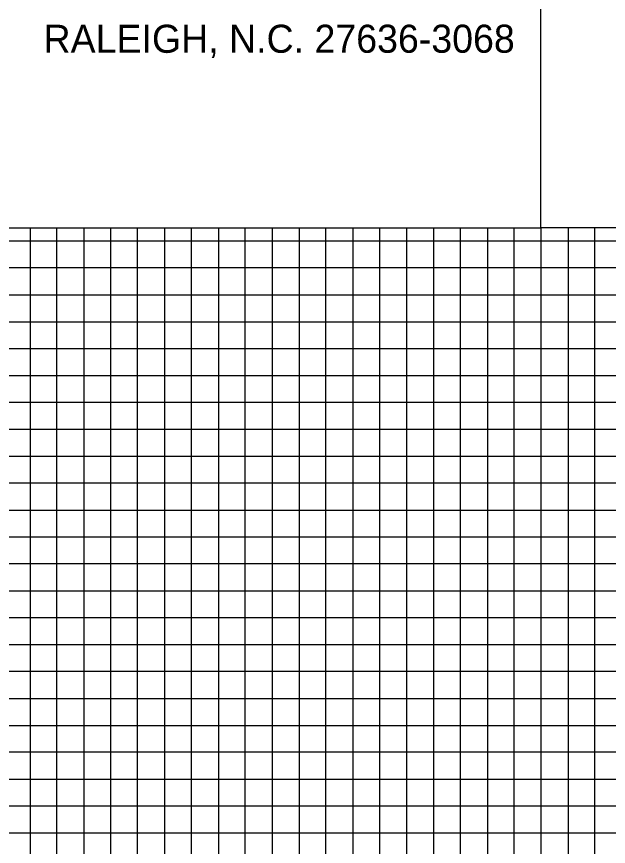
# Model space of a CAD drawing. Extents: x 2431000 to 2534000, y 645879 to 714000.
# Drawn here: x 2468176.3 to 2468286.3, y 669664.6 to 669818.8 of the extents above; entities that cross this region are included whole.
import ezdxf

# ---------------------------------------------------------------- set-up
doc = ezdxf.new("R2010")
doc.units = 0
for name, color, linetype in [('KHA_LOGO', 7, 'Continuous'), ('Sheet Profile CELL', 7, 'Continuous'), ('Sheet Profile Grid Major CELL', 7, 'Continuous'), ('Sheet Profile Grid Middle CELL', 7, 'Continuous'), ('Sheet Profile Grid Minor CELL', 7, 'Continuous')]:
    doc.layers.add(name, color=color, linetype=linetype)

msp = doc.modelspace()

# ---------------------------------------------------------------- linework, layer by layer
at = {"layer": 'KHA_LOGO'}
msp.add_lwpolyline([(2468173.7, 669779.51), (2468273.7, 669779.51), (2468273.7, 669917.06), (2468173.7, 669917.06)], close=True, dxfattribs=at)
at = {"layer": 'Sheet Profile CELL'}
msp.add_lwpolyline([(2468273.7, 669892.01), (2468373.75, 669892.01), (2468373.75, 669779.51), (2468273.7, 669779.51)], close=True, dxfattribs=at)
at = {"layer": 'Sheet Profile Grid Major CELL'}
for points in [[(2468173.75, 669817.06), (2466973.75, 669817.06), (2466973.75, 669767.06), (2468473.75, 669767.06)], [(2468273.75, 669817.06), (2468273.7, 669817.06)], [(2468223.75, 669779.51), (2468223.75, 669417.06), (2468273.75, 669417.06), (2468273.75, 669779.51)], [(2468473.75, 669717.06), (2466973.75, 669717.06), (2466973.75, 669667.06), (2468473.75, 669667.06)]]:
    msp.add_lwpolyline(points, dxfattribs=at)
at = {"layer": 'Sheet Profile Grid Middle CELL'}
for points in [[(2467698.75, 669917.06), (2467748.75, 669917.06), (2467748.75, 669417.06), (2467798.75, 669417.06), (2467798.75, 669917.06), (2467848.75, 669917.06), (2467848.75, 669417.06), (2467898.75, 669417.06), (2467898.75, 669917.06), (2467948.75, 669917.06), (2467948.75, 669417.06), (2467998.75, 669417.06), (2467998.75, 669917.06), (2468048.75, 669917.06), (2468048.75, 669417.06), (2468098.75, 669417.06), (2468098.75, 669917.06), (2468148.75, 669917.06), (2468148.75, 669417.06), (2468198.75, 669417.06), (2468198.75, 669779.51)], [(2468248.75, 669779.51), (2468248.75, 669417.06), (2468298.75, 669417.06), (2468298.75, 669779.51)], [(2468473.75, 669742.06), (2466973.75, 669742.06), (2466973.75, 669692.06), (2468298.75, 669692.06)]]:
    msp.add_lwpolyline(points, dxfattribs=at)
at = {"layer": 'Sheet Profile Grid Minor CELL'}
for p, q in [((2468423.75, 669777.06), (2467023.75, 669777.06)), ((2468423.75, 669772.06), (2467023.75, 669772.06)), ((2467023.75, 669762.06), (2468423.75, 669762.06)), ((2468423.75, 669757.06), (2467023.75, 669757.06)), ((2467023.75, 669752.06), (2468423.75, 669752.06)), ((2468423.75, 669732.06), (2467023.75, 669732.06)), ((2467023.75, 669727.06), (2468423.75, 669727.06)), ((2468423.75, 669707.06), (2467023.75, 669707.06)), ((2467023.75, 669702.06), (2468423.75, 669702.06)), ((2468423.75, 669682.06), (2467023.75, 669682.06)), ((2467023.75, 669677.06), (2468423.75, 669677.06)), ((2468423.75, 669672.06), (2467023.75, 669672.06))]:
    msp.add_line(p, q, dxfattribs=at)
for points in [[(2468273.7, 669812.06), (2468273.75, 669812.06)], [(2468273.75, 669806.96), (2468273.7, 669806.96)], [(2468273.7, 669802.06), (2468273.75, 669802.06)], [(2468273.75, 669797.06), (2468273.7, 669797.06)], [(2468273.7, 669787.06), (2468273.75, 669787.06)], [(2468178.75, 669779.51), (2468178.75, 669417.06), (2468183.75, 669417.06), (2468183.75, 669779.51)], [(2468188.75, 669779.51), (2468188.75, 669417.06), (2468193.75, 669417.06), (2468193.75, 669779.51)], [(2468203.75, 669779.51), (2468203.75, 669417.06), (2468208.75, 669417.06), (2468208.75, 669779.51)], [(2468213.75, 669779.51), (2468213.75, 669417.06), (2468218.75, 669417.06), (2468218.75, 669779.51)], [(2468228.75, 669779.51), (2468228.75, 669417.06), (2468233.75, 669417.06), (2468233.75, 669779.51)], [(2468238.75, 669779.51), (2468238.75, 669417.06), (2468243.75, 669417.06), (2468243.75, 669779.51)], [(2468253.75, 669779.51), (2468253.75, 669417.06), (2468258.75, 669417.06), (2468258.75, 669779.51)], [(2468263.75, 669779.51), (2468263.75, 669417.06), (2468268.75, 669417.06), (2468268.75, 669779.51)], [(2468278.75, 669779.51), (2468278.75, 669417.06), (2468283.75, 669417.06), (2468283.75, 669779.51)], [(2468423.75, 669747.06), (2467023.75, 669747.06), (2467023.75, 669737.06), (2468423.75, 669737.06)], [(2468423.75, 669722.06), (2467023.75, 669722.06), (2467023.75, 669712.06), (2468423.75, 669712.06)], [(2468423.75, 669697.06), (2467023.75, 669697.06), (2467023.75, 669687.06), (2468423.75, 669687.06)]]:
    msp.add_lwpolyline(points, dxfattribs=at)

# ---------------------------------------------------------------- texts
at = {"layer": 'KHA_LOGO'}
msp.add_text('RALEIGH, N.C. 27636-3068', height=5.2139, rotation=0.0107, dxfattribs=at).set_placement((2468181.26, 669812.05))

doc.saveas('drawing.dxf')
